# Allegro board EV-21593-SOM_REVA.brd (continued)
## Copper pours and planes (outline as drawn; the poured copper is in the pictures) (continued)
$13N133 on TOP (solid shape): 44.96,96.65 42.29,96.65 41.53,97.41 38.86,97.41 37.72,96.27 35.94,96.27 35.94,99.49 36.58,100.13 44.96,100.13

Small or netless copper shapes (teardrops, artwork), in the pictures only: 1756 on TOP, 890 on BOTTOM, 241 on L4_SIG, 252 on L5_SIG

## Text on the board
BOTTOM: LAYER 8  BOTTOM SIDE | 8  OF  14
Board Geometry/Soldermask Bottom: SOLDER MASK  BOTTOM SIDE | 10  OF  14
Ref Des/Silkscreen Bottom: EV-21593-SOM REV A | ANALOG DEVICES INC. (C)2020 | DESIGNED BY | SILKSCREEN   BOTTOM SIDE | 12  OF  14 | SERIAL NO. | REV | BOM
TOP: LAYER 1  TOP SIDE | 1  OF  14
Board Geometry/Soldermask Top: SOLDER MASK  TOP SIDE | 9  OF  14
Ref Des/Silkscreen Top: BOOT MODE | TX | RX | FAULT | RESET | PWR | UART | POWER | DEBUG | SILKSCREEN   TOP SIDE | 11  OF  14 | EV-21593-SOM REV A
L2_PWR: LAYER 2 POWER PLANE | 2  OF  14
L3_GND: LAYER 3 GROUND PLANE | 3  OF  14
L4_SIG: LAYER 4 INTERNAL SIGNAL | 4  OF  14
L5_SIG: LAYER 5  INTERNAL SIGNAL | 5  OF  14
L6_GND: LAYER 6 GROUND PLANE | 6  OF  14
L7_PWR: LAYER 7 POWER PLANE | 7  OF  14
DIMENSION: 5.000 | 0.250 | 0.098 | 0.774 | 0.552 | 3.500 | FULL R TYP | 0.500 TYP | V-SCORE (4x)
ALL: MATERIAL | FINISH | UNLESS OTHERWISE SPECIFIED | DIMENSIONS ARE IN INCHES | TOLERANCES ARE : | .XX +/- .010 .XXX +/- .005 | DO NOT SCALE THIS DRAWING | DRAWN | CHECKED | ENGINEERING | QUALITY | MANUFACTURING | CONTRACT NO. | APPROVALS | 04/24/20 | DATE | SCALE | SIZE | DWG. NO. | 1 : 1 | 2 Elizabeth Drive | Chelmsford, MA 01824 | SHEET | REV. | C.C.D. | REV | A | DESCRIPTION OF CHANGE | NEW RELEASE | DRFTR | APPROVED | REVISIONS | EV-21593-SOM | B | EV-21593-SOM_PCB
